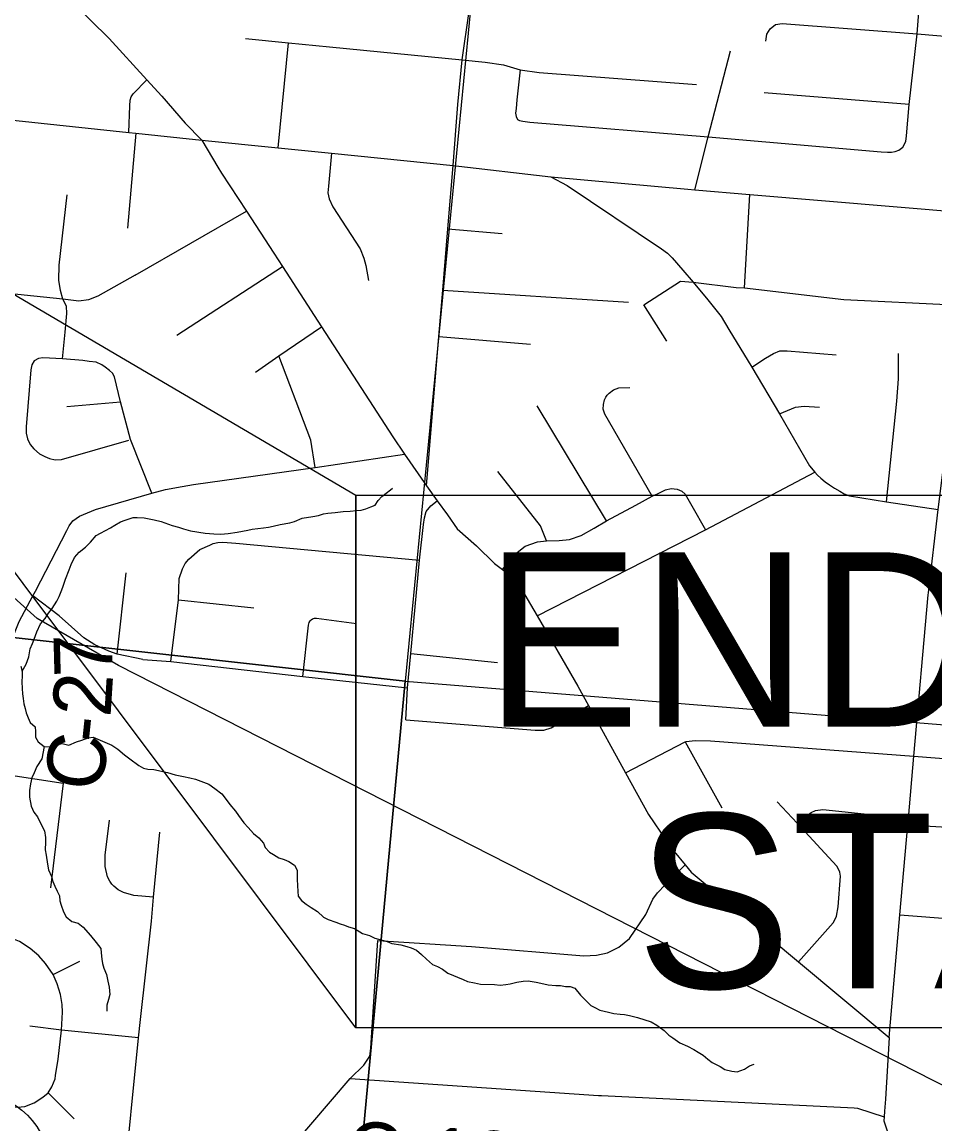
# Model space of a CAD drawing. Extents: x 0 to 34, y 0 to 22.
# Drawn here: x 7.479 to 8.369, y 17.836 to 18.91 of the extents above; entities that cross this region are included whole.
import ezdxf

# ---------------------------------------------------------------- set-up
doc = ezdxf.new("R2010")
doc.units = 0
for name, color, linetype in [('GM_X_City_Street', 7, 'Continuous'), ('GM_X_Corporation', 7, 'Continuous'), ('GM_X_County_Road', 7, 'Continuous'), ('GM_X_County_Road_Text', 7, 'Continuous'), ('GM_X_Minor_River', 7, 'Continuous'), ('GM_X_Rail_Line', 7, 'Continuous'), ('GM_X_State_Route', 7, 'Continuous'), ('GM_X_Township_Road', 7, 'Continuous'), ('GM_X_Unincorporated', 7, 'Continuous'), ('SH_Masking', 7, 'Continuous'), ('SH_Text', 7, 'Continuous')]:
    doc.layers.add(name, color=color, linetype=linetype)

msp = doc.modelspace()

# ---------------------------------------------------------------- linework, layer by layer
at = {"layer": 'GM_X_City_Street'}
for p, q in [((7.7288, 18.7873), (7.739, 18.8897)), ((8.3438, 18.8296), (8.2027, 18.8408)), ((7.5901, 18.8016), (7.582, 18.7089)), ((8.1833, 18.6508), (8.1886, 18.7419)), ((7.5895, 18.6632), (7.6979, 18.7257)), ((7.8943, 18.7083), (7.9471, 18.7038)), ((7.6302, 18.6047), (7.7331, 18.6717)), ((7.8893, 18.6487), (8.0705, 18.6368)), ((7.5186, 18.5817), (7.5214, 18.6076)), ((7.8855, 18.6033), (7.9749, 18.5959)), ((7.523, 18.5351), (7.5752, 18.5397)), ((8.0489, 18.4237), (7.9812, 18.5357)), ((7.6316, 18.3469), (7.7051, 18.339)), ((7.8582, 18.2945), (7.9428, 18.2858)), ((8.1257, 18.2082), (8.1612, 18.1439)), ((8.3349, 18.0398), (8.3893, 18.0355))]:
    msp.add_line(p, q, dxfattribs=at)
for points in [[(8.334, 18.785), (8.3377, 18.7878), (8.3408, 18.7934), (8.3415, 18.7989), (8.3438, 18.8296), (8.3518, 18.8983), (8.3561, 18.9539), (8.3614, 19.0106), (8.3671, 19.0633), (8.3678, 19.0737), (8.3662, 19.0839), (8.3627, 19.095), (8.3619, 19.105), (8.365, 19.1341)], [(8.2041, 18.8912), (8.2052, 18.8981), (8.2084, 18.9033), (8.2137, 18.9076), (8.2203, 18.9086), (8.3518, 18.8983), (8.4206, 18.8926), (8.4972, 18.886), (8.6065, 18.8774)], [(7.697, 18.894), (7.739, 18.8897), (7.7789, 18.8856), (7.9083, 18.873), (7.9308, 18.8708), (7.9486, 18.8683), (7.9647, 18.8635), (7.9834, 18.8608), (8.1366, 18.8491)], [(8.1349, 18.7465), (8.1481, 18.7981), (8.1697, 18.882)], [(7.9647, 18.8635), (7.9616, 18.834), (7.9608, 18.8256), (7.9603, 18.8212), (7.961, 18.8177), (7.9622, 18.8149), (7.9642, 18.814), (7.9674, 18.8133), (7.9741, 18.8122), (8.1481, 18.7981), (8.3168, 18.7834), (8.3228, 18.7831), (8.3267, 18.7832), (8.3302, 18.7836), (8.334, 18.785)], [(7.5834, 18.8023), (7.5842, 18.8281), (7.5847, 18.8338), (7.5856, 18.837), (7.5875, 18.8398), (7.601, 18.8536)], [(7.7808, 18.7821), (7.7779, 18.7501), (7.7773, 18.7434), (7.7787, 18.7375), (7.7822, 18.7299), (7.8087, 18.689), (7.8125, 18.6798), (7.8142, 18.6726), (7.8168, 18.6581)], [(8.1077, 18.5988), (8.0852, 18.6344), (8.1209, 18.6575), (8.1334, 18.6564), (8.1752, 18.6512), (8.1833, 18.6508), (8.2803, 18.6396), (8.3873, 18.6343), (8.3921, 18.634), (8.4317, 18.6321), (8.4498, 18.6296), (8.4803, 18.6219), (8.5774, 18.6038), (8.64, 18.5923), (8.6474, 18.5915), (8.7239, 18.5832), (8.7443, 18.5809), (8.7578, 18.5775), (8.7707, 18.5741), (8.7846, 18.5685), (8.8001, 18.5621), (8.8164, 18.556)], [(7.7067, 18.5688), (7.7296, 18.5845), (7.7711, 18.613)], [(7.6056, 18.4508), (7.5851, 18.5029), (7.5752, 18.5397), (7.5692, 18.564), (7.5674, 18.5677), (7.5645, 18.5704), (7.5601, 18.5736), (7.5571, 18.5757), (7.5515, 18.5784), (7.5447, 18.5792), (7.5384, 18.58), (7.5186, 18.5817), (7.4995, 18.5827), (7.4952, 18.582), (7.4911, 18.5797), (7.4889, 18.5759), (7.4879, 18.5709), (7.4834, 18.5154), (7.4834, 18.5091), (7.4847, 18.5036), (7.4872, 18.4981), (7.4907, 18.4938), (7.4961, 18.4892), (7.5014, 18.4866), (7.5059, 18.4844), (7.5115, 18.4831), (7.5178, 18.4834), (7.5832, 18.5024)], [(7.7651, 18.4757), (7.7607, 18.5023), (7.7571, 18.5119), (7.7296, 18.5845)], [(8.1905, 18.5736), (8.2038, 18.5823), (8.2118, 18.587), (8.218, 18.5895), (8.2249, 18.5895), (8.2729, 18.5857)], [(8.3219, 18.4423), (8.332, 18.5405), (8.3336, 18.562), (8.3334, 18.5869)], [(8.0936, 18.4477), (8.0474, 18.5277), (8.0457, 18.5325), (8.046, 18.537), (8.047, 18.5416), (8.0482, 18.5443), (8.0497, 18.5461), (8.0514, 18.5483), (8.0557, 18.5515), (8.061, 18.5534), (8.0716, 18.5538)], [(8.2174, 18.5281), (8.2331, 18.5344), (8.2417, 18.5355), (8.2566, 18.5346)], [(7.9905, 18.4044), (7.9845, 18.4189), (7.943, 18.4717)], [(7.9812, 18.3312), (8.1454, 18.415), (8.252, 18.4713)], [(7.9477, 18.3762), (7.9602, 18.3915), (7.9695, 18.3989), (7.9818, 18.4034), (7.9905, 18.4044), (8.0029, 18.4046), (8.0129, 18.4057), (8.0241, 18.4094), (8.0369, 18.4166), (8.0489, 18.4237), (8.0776, 18.439), (8.0936, 18.4477), (8.0993, 18.4505), (8.1064, 18.4538), (8.112, 18.4554), (8.1178, 18.4547), (8.1223, 18.4525), (8.1255, 18.4496), (8.1321, 18.4384), (8.1454, 18.415)], [(7.6243, 18.2867), (7.6316, 18.3469), (7.6324, 18.3674), (7.6356, 18.3768), (7.6384, 18.382), (7.6417, 18.3863), (7.6526, 18.3958), (7.6622, 18.4001), (7.6656, 18.4015), (7.67, 18.4026), (7.6749, 18.4029), (7.6876, 18.402), (7.8667, 18.3855)], [(7.7529, 18.2719), (7.7583, 18.3222), (7.759, 18.3245), (7.76, 18.3263), (7.761, 18.3274), (7.7625, 18.3282), (7.7643, 18.3288), (7.7661, 18.3288), (7.8051, 18.3236)], [(7.5969, 18.2887), (7.6243, 18.2867), (7.7529, 18.2719), (7.855, 18.2609)], [(7.8532, 18.2297), (7.9793, 18.2196), (7.9877, 18.2196), (7.995, 18.222), (8.0314, 18.2438)], [(8.0676, 18.1781), (8.1257, 18.2082), (8.1267, 18.2088), (8.1355, 18.2096), (8.1503, 18.2092), (8.3486, 18.1943), (8.3943, 18.1909), (8.4065, 18.1898), (8.426, 18.1823), (8.4377, 18.1809), (8.5151, 18.1759), (8.54, 18.1713), (8.5951, 18.1657), (8.6237, 18.1628), (8.6461, 18.1632), (8.6701, 18.1659), (8.6873, 18.1673), (8.6994, 18.1658), (8.7228, 18.1613), (8.7363, 18.1545)], [(8.2361, 17.9938), (8.2699, 18.032), (8.2712, 18.0342), (8.2731, 18.0383), (8.2749, 18.0474), (8.2769, 18.0774), (8.2767, 18.0792), (8.2763, 18.0812), (8.2753, 18.0837), (8.2735, 18.0873), (8.2347, 18.129), (8.2153, 18.1499)], [(8.2347, 18.129), (8.2484, 18.1394), (8.2527, 18.1415), (8.2599, 18.1425), (8.3432, 18.1335)], [(8.3427, 18.1275), (8.5175, 18.1169), (8.5891, 18.112), (8.8063, 18.0969)]]:
    msp.add_lwpolyline(points, dxfattribs=at)
at = {"layer": 'GM_X_Corporation'}
for points in [[(7.955, 19.3167), (7.9506, 19.2737), (7.8526, 18.2675), (6.8431, 18.3799), (6.9413, 19.3834), (7.3067, 19.3446), (7.3077, 19.388)], [(8.9, 18.6915), (8.9, 19.1876), (7.9506, 19.2737), (7.8526, 18.2675), (8.8482, 18.1868)], [(6.8431, 18.3799), (7.8526, 18.2675), (7.7575, 17.2431), (6.7271, 17.3517)], [(8.8482, 18.1868), (8.7485, 17.1931), (7.7575, 17.2431), (7.8526, 18.2675)]]:
    msp.add_lwpolyline(points, close=True, dxfattribs=at)
at = {"layer": 'GM_X_County_Road'}
msp.add_line((7.8199, 17.92), (7.826, 18.0147), dxfattribs=at)
for points in [[(7.8734, 18.4577), (7.8855, 18.6033), (7.8893, 18.6487), (7.8943, 18.7083), (7.8994, 18.7701), (7.9041, 18.8297), (7.9083, 18.873), (7.9288, 19.0156), (7.9329, 19.0716), (7.937, 19.109), (7.9413, 19.1588), (7.9429, 19.17), (7.9471, 19.2123), (7.9531, 19.2698), (7.9538, 19.2787), (7.957, 19.3132), (7.96, 19.3445), (7.963, 19.3715), (7.9632, 19.3734)], [(7.3625, 18.8296), (7.4583, 18.8156), (7.5834, 18.8023), (7.5901, 18.8016), (7.6544, 18.7948)], [(7.6544, 18.7948), (7.7288, 18.7873), (7.7808, 18.7821), (7.8994, 18.7701), (7.9947, 18.7591)], [(8.3626, 18.3515), (8.3628, 18.3536), (8.3722, 18.4349), (8.3802, 18.4994), (8.3834, 18.5557), (8.3921, 18.634), (8.4021, 18.724), (8.4086, 18.7914), (8.4088, 18.7934)], [(7.9947, 18.7591), (8.1282, 18.747), (8.1349, 18.7465), (8.1886, 18.7419), (8.4021, 18.724)], [(7.9947, 18.7591), (8.0106, 18.7506), (8.1026, 18.689), (8.1083, 18.6847), (8.1131, 18.68), (8.1234, 18.6682), (8.1334, 18.6564)], [(8.1334, 18.6564), (8.1476, 18.6393), (8.1608, 18.6229), (8.1681, 18.6104), (8.1905, 18.5736), (8.2174, 18.5281), (8.2467, 18.4775), (8.252, 18.4713), (8.2546, 18.4683), (8.2577, 18.4652), (8.262, 18.4617), (8.2664, 18.4588), (8.2712, 18.4557), (8.2764, 18.4525), (8.2807, 18.4501), (8.2859, 18.4482), (8.3219, 18.4423), (8.3722, 18.4349)], [(7.6352, 18.4571), (7.6462, 18.459), (7.7651, 18.4757), (7.8521, 18.4887)], [(7.6056, 18.4508), (7.6192, 18.4542), (7.6352, 18.4571)], [(7.5228, 18.4144), (7.5253, 18.419), (7.5289, 18.4238), (7.5354, 18.4282), (7.5508, 18.4348), (7.6056, 18.4508)], [(7.8532, 18.2297), (7.855, 18.2609), (7.8582, 18.2945), (7.8667, 18.3855), (7.8707, 18.4201), (7.8716, 18.4266), (7.8732, 18.4329), (7.8776, 18.4384), (7.884, 18.4431)], [(7.4678, 18.3034), (7.4763, 18.3256), (7.4897, 18.3507), (7.4923, 18.3553), (7.5228, 18.4144)], [(8.3243, 17.92), (8.3349, 18.0398), (8.3427, 18.1275), (8.3432, 18.1335), (8.3486, 18.1943), (8.3626, 18.3515)], [(7.826, 18.0147), (7.9172, 18.0089), (8.0269, 17.9998), (8.0392, 18.0005), (8.0498, 18.0027), (8.0608, 18.0083), (8.0714, 18.0165), (8.0874, 18.0401), (8.0942, 18.0549), (8.0988, 18.0612), (8.106, 18.0689), (8.1257, 18.0884)], [(7.7992, 17.8803), (7.8124, 17.8932), (7.8181, 17.9021), (7.8192, 17.9097), (7.8199, 17.92)], [(7.707, 17.2464), (7.7156, 17.3082), (7.7212, 17.359), (7.7233, 17.3801), (7.7234, 17.3963), (7.7199, 17.416), (7.7156, 17.4332), (7.6975, 17.4916), (7.6871, 17.529), (7.6744, 17.5719), (7.6604, 17.6215), (7.6587, 17.6304), (7.6577, 17.6397), (7.658, 17.6496), (7.6589, 17.6584), (7.6607, 17.6669), (7.664, 17.6782), (7.6701, 17.6956), (7.6764, 17.7122), (7.6912, 17.7472), (7.6994, 17.7637), (7.7415, 17.8129), (7.7992, 17.8803)], [(7.7992, 17.8803), (8.041, 17.8637), (8.0441, 17.8635)], [(8.0441, 17.8635), (8.2904, 17.8516), (8.2935, 17.8512), (8.3195, 17.8427)]]:
    msp.add_lwpolyline(points, dxfattribs=at)
at = {"layer": 'GM_X_Minor_River'}
for points in [[(7.4795, 18.2772), (7.4831, 18.2839), (7.486, 18.2911), (7.4873, 18.299), (7.4894, 18.3043), (7.491, 18.3085), (7.4935, 18.3156), (7.4971, 18.3235), (7.5018, 18.3287), (7.505, 18.3336), (7.5086, 18.3384), (7.5133, 18.3455), (7.5153, 18.3501), (7.5174, 18.355), (7.519, 18.3591), (7.5215, 18.367), (7.5252, 18.3761), (7.5272, 18.3813), (7.5304, 18.3881), (7.5348, 18.3933), (7.541, 18.3981), (7.5461, 18.4029), (7.5516, 18.4096), (7.5558, 18.4118), (7.5655, 18.4168), (7.5697, 18.4194), (7.5751, 18.4227), (7.5797, 18.4244), (7.5874, 18.4269), (7.5916, 18.4271), (7.5984, 18.4266), (7.6079, 18.4248), (7.6147, 18.4231), (7.6256, 18.4193), (7.6316, 18.4176), (7.6365, 18.416), (7.6433, 18.4139), (7.6577, 18.4116), (7.6661, 18.411), (7.6729, 18.4108), (7.6802, 18.4113), (7.6889, 18.4126), (7.6993, 18.4146), (7.7035, 18.4156), (7.7092, 18.4162), (7.7145, 18.4169), (7.7195, 18.4175), (7.7241, 18.4185), (7.731, 18.4202), (7.7401, 18.4219), (7.7447, 18.4232), (7.7524, 18.4265), (7.7627, 18.4281), (7.7681, 18.4291), (7.7731, 18.4305), (7.7773, 18.4311), (7.7845, 18.432), (7.7922, 18.433), (7.799, 18.4332), (7.8051, 18.4337), (7.8097, 18.434), (7.8143, 18.4354), (7.8193, 18.4375), (7.8235, 18.4389), (7.8263, 18.4434), (7.8298, 18.4475), (7.8384, 18.4541), (7.8403, 18.4556)], [(7.4781, 18.2822), (7.4795, 18.2772), (7.4794, 18.2726), (7.4789, 18.2669), (7.4795, 18.2604), (7.4797, 18.2551), (7.4803, 18.2505), (7.4809, 18.2455), (7.4823, 18.2409), (7.4834, 18.2367), (7.4851, 18.2317), (7.4873, 18.2271), (7.4921, 18.2231), (7.4924, 18.2185), (7.4922, 18.2128), (7.4951, 18.2082), (7.5007, 18.2038), (7.5076, 18.2033), (7.5141, 18.2057), (7.5183, 18.2068), (7.5247, 18.2051), (7.5324, 18.2083), (7.5374, 18.21), (7.5436, 18.2122), (7.5485, 18.2128), (7.5666, 18.205), (7.5725, 18.2011), (7.5792, 18.1955), (7.5844, 18.1916), (7.593, 18.1853), (7.5975, 18.1825), (7.6017, 18.1816), (7.6077, 18.1814), (7.6123, 18.1805), (7.6164, 18.1793), (7.621, 18.1784), (7.6285, 18.1763), (7.6365, 18.1745), (7.6429, 18.1732), (7.6482, 18.1719), (7.6561, 18.169), (7.6614, 18.167), (7.667, 18.163), (7.674, 18.1578), (7.6781, 18.152), (7.6817, 18.1473), (7.6873, 18.1407), (7.6902, 18.1365), (7.6953, 18.1295), (7.6998, 18.1248), (7.7049, 18.1189), (7.7101, 18.1146), (7.7146, 18.1095), (7.7163, 18.1052), (7.7204, 18.1009), (7.7245, 18.0985), (7.7294, 18.0954), (7.7347, 18.0937), (7.7392, 18.0917), (7.7448, 18.0881), (7.7473, 18.0834), (7.7475, 18.0743), (7.7477, 18.0682), (7.7479, 18.0625), (7.7485, 18.0579), (7.7515, 18.0536), (7.7563, 18.05), (7.7612, 18.0469), (7.7671, 18.0429), (7.7731, 18.0374)], [(7.5007, 18.2038), (7.4985, 18.1917), (7.4937, 18.1842), (7.4909, 18.1782), (7.4889, 18.1733), (7.4876, 18.1673), (7.4866, 18.1608), (7.4865, 18.1543), (7.4881, 18.1455), (7.4906, 18.1397), (7.4943, 18.1351), (7.4979, 18.1277), (7.5012, 18.1215), (7.5021, 18.115), (7.502, 18.1105), (7.5018, 18.1029), (7.5028, 18.0979), (7.5041, 18.0891), (7.5051, 18.0837), (7.5079, 18.0772), (7.5093, 18.0722), (7.5111, 18.0676), (7.5136, 18.0629), (7.5158, 18.0583), (7.516, 18.0533), (7.5175, 18.0491), (7.5196, 18.0426), (7.5221, 18.0376), (7.5277, 18.0332), (7.5341, 18.0315), (7.5389, 18.0276), (7.5459, 18.0194), (7.5515, 18.0127), (7.5559, 18.0069), (7.5565, 18.0027), (7.5571, 17.9966), (7.5577, 17.9924), (7.5591, 17.9878), (7.5616, 17.9816), (7.563, 17.9751), (7.564, 17.9693), (7.5649, 17.9621), (7.5636, 17.9572), (7.562, 17.9515), (7.5618, 17.9458)], [(7.7731, 18.0374), (7.7776, 18.035), (7.7851, 18.0325), (7.7892, 18.0308), (7.7934, 18.0296), (7.7975, 18.0279), (7.8032, 18.0263), (7.811, 18.0215), (7.8178, 18.0194), (7.8231, 18.017), (7.8352, 18.0136), (7.8397, 18.0119), (7.8484, 18.0105), (7.8544, 18.0088), (7.8586, 18.0076), (7.8638, 18.0051), (7.8687, 18.0012), (7.8735, 17.9965), (7.8794, 17.9914), (7.8843, 17.9893), (7.8892, 17.9869), (7.8944, 17.983), (7.9091, 17.9768), (7.9136, 17.9748), (7.9204, 17.9735), (7.9261, 17.9722), (7.9398, 17.9718), (7.9454, 17.9713), (7.9508, 17.9719), (7.955, 17.9725), (7.9615, 17.9742), (7.9676, 17.9752), (7.9726, 17.9754), (7.9805, 17.9741), (7.9877, 17.9724), (7.9922, 17.9715), (7.9994, 17.9709), (8.004, 17.9708), (8.0089, 17.9699), (8.0135, 17.9697), (8.018, 17.9681), (8.0235, 17.9615), (8.0335, 17.9513), (8.0376, 17.9493), (8.0425, 17.9468), (8.0508, 17.9447), (8.0561, 17.9434), (8.0622, 17.9429), (8.0664, 17.9424), (8.0713, 17.9415), (8.0792, 17.9397), (8.0924, 17.9355), (8.098, 17.9323), (8.1051, 17.9268), (8.1096, 17.9225), (8.1137, 17.9197), (8.1204, 17.915), (8.1279, 17.9117), (8.1339, 17.9085), (8.1384, 17.9057), (8.1432, 17.9029), (8.1477, 17.899), (8.1518, 17.8958), (8.1597, 17.8918), (8.1642, 17.889), (8.171, 17.8873), (8.1763, 17.8867), (8.1836, 17.8892), (8.1882, 17.8925), (8.1928, 17.8943)]]:
    msp.add_lwpolyline(points, dxfattribs=at)
at = {"layer": 'GM_X_Rail_Line'}
msp.add_lwpolyline([(8.5673, 17.785), (8.3852, 17.869), (7.5731, 18.2826), (7.4939, 18.3285), (7.448, 18.3697)], dxfattribs=at)
at = {"layer": 'GM_X_State_Route'}
msp.add_line((7.6544, 18.7948), (7.6701, 18.7686), dxfattribs=at)
for points in [[(7.3173, 19.1096), (7.337, 19.088), (7.3546, 19.0676), (7.3683, 19.054), (7.3928, 19.0323), (7.458, 18.9838), (7.5074, 18.9448), (7.5274, 18.9299), (7.5641, 18.894), (7.601, 18.8536), (7.6155, 18.8378), (7.6383, 18.8113), (7.6544, 18.7948)], [(7.6701, 18.7686), (7.6738, 18.7625), (7.6979, 18.7257), (7.7248, 18.6846), (7.7331, 18.6717), (7.7711, 18.613), (7.8405, 18.5056), (7.8521, 18.4887), (7.8734, 18.4577), (7.884, 18.4431), (7.8938, 18.4295), (7.9033, 18.416), (7.9221, 18.3993), (7.9397, 18.3823), (7.9477, 18.3762), (7.951, 18.3737), (7.9629, 18.3627), (7.9812, 18.3312), (8.0209, 18.2627), (8.0314, 18.2438), (8.0676, 18.1781), (8.09, 18.1374), (8.1072, 18.1121), (8.1149, 18.1013), (8.1257, 18.0884), (8.1316, 18.0814), (8.2361, 17.9938), (8.3243, 17.92), (8.3208, 17.8601), (8.3198, 17.8484), (8.3195, 17.8427), (8.3192, 17.8389), (8.3225, 17.8292)]]:
    msp.add_lwpolyline(points, dxfattribs=at)
at = {"layer": 'GM_X_Township_Road'}
for p, q in [((7.572, 18.2938), (7.5806, 18.373)), ((7.4597, 18.177), (7.5192, 18.1681)), ((7.5192, 18.1681), (7.5069, 18.0659)), ((7.5097, 17.9816), (7.5355, 17.9944)), ((7.5176, 17.9273), (7.4867, 17.9311)), ((7.5926, 17.9197), (7.5176, 17.9273)), ((7.5046, 17.8662), (7.53, 17.8408))]:
    msp.add_line(p, q, dxfattribs=at)
for points in [[(7.5214, 18.6076), (7.5229, 18.6258), (7.5225, 18.633), (7.519, 18.6398), (7.5166, 18.6483), (7.5152, 18.6584), (7.5153, 18.6729), (7.5231, 18.7415)], [(7.5895, 18.6632), (7.5532, 18.6427), (7.544, 18.6393), (7.5346, 18.6378), (7.519, 18.6398), (7.4464, 18.6474), (7.38, 18.6551)], [(7.5969, 18.2887), (7.572, 18.2938), (7.5637, 18.2968), (7.5503, 18.303), (7.5396, 18.3097), (7.5153, 18.3312), (7.4897, 18.3507)], [(7.6074, 18.057), (7.5881, 18.0587), (7.5781, 18.0614), (7.5728, 18.0641), (7.5686, 18.0675), (7.5669, 18.0697), (7.5649, 18.0725), (7.5625, 18.0766), (7.5602, 18.0869), (7.5603, 18.098), (7.5645, 18.1321)], [(7.5782, 17.7728), (7.5926, 17.9197), (7.5946, 17.9376), (7.6053, 18.0335), (7.6074, 18.057), (7.6134, 18.1202)], [(7.4265, 17.857), (7.4665, 17.8524), (7.4748, 17.8523), (7.4819, 17.8528), (7.4909, 17.8563), (7.4995, 17.862), (7.5046, 17.8662), (7.5083, 17.8719), (7.5114, 17.8798), (7.5118, 17.883), (7.5145, 17.8989), (7.5176, 17.9273), (7.5188, 17.9448), (7.5182, 17.9522), (7.5166, 17.962), (7.5136, 17.9726), (7.5097, 17.9816), (7.502, 17.9924), (7.4956, 17.9998), (7.4873, 18.007), (7.4767, 18.0138), (7.4653, 18.0184), (7.4555, 18.0207), (7.4448, 18.0229)]]:
    msp.add_lwpolyline(points, dxfattribs=at)
at = {"layer": 'GM_X_Unincorporated'}
msp.add_circle((7.4318, 17.7918), 0.0744, dxfattribs=at)
at = {"layer": 'SH_Masking'}
msp.add_lwpolyline([(7.8046, 18.4489), (9.562, 18.4489), (9.562, 17.9295), (7.8046, 17.9295)], close=True, dxfattribs=at)
at = {"layer": 'SH_Text'}
for points in [[(7.8046, 17.9295), (7.1101, 18.8565), (7.8046, 18.4489)], [(7.8046, 18.4489), (9.562, 18.4489), (9.562, 17.9295), (7.8046, 17.9295)], [(7.8046, 18.4489), (9.562, 18.4489), (9.562, 17.9295), (7.8046, 17.9295)]]:
    msp.add_lwpolyline(points, close=True, dxfattribs=at)

# ---------------------------------------------------------------- texts
at = {"layer": 'GM_X_County_Road_Text'}
for s, height, rotation, p in [('7', 0.0568, 91.5631, (7.5677, 18.2722)), ('2', 0.0568, 86.3745, (7.5654, 18.2316)), ('-', 0.0568, 83.9783, (7.5628, 18.2058)), ('C', 0.0568, 83.4934, (7.5574, 18.1589)), ('C-126', 0.05682, 355.8754, (7.7931, 17.7826))]:
    msp.add_text(s, height=height, rotation=rotation, dxfattribs=at).set_placement(p)
at = {"layer": 'SH_Text'}
for s, p in [('END PROJECT', (7.93, 18.2232)), ('STA. 59+00', (8.0777, 17.9682))]:
    msp.add_text(s, height=0.17, dxfattribs=at).set_placement(p)

doc.saveas('drawing.dxf')
